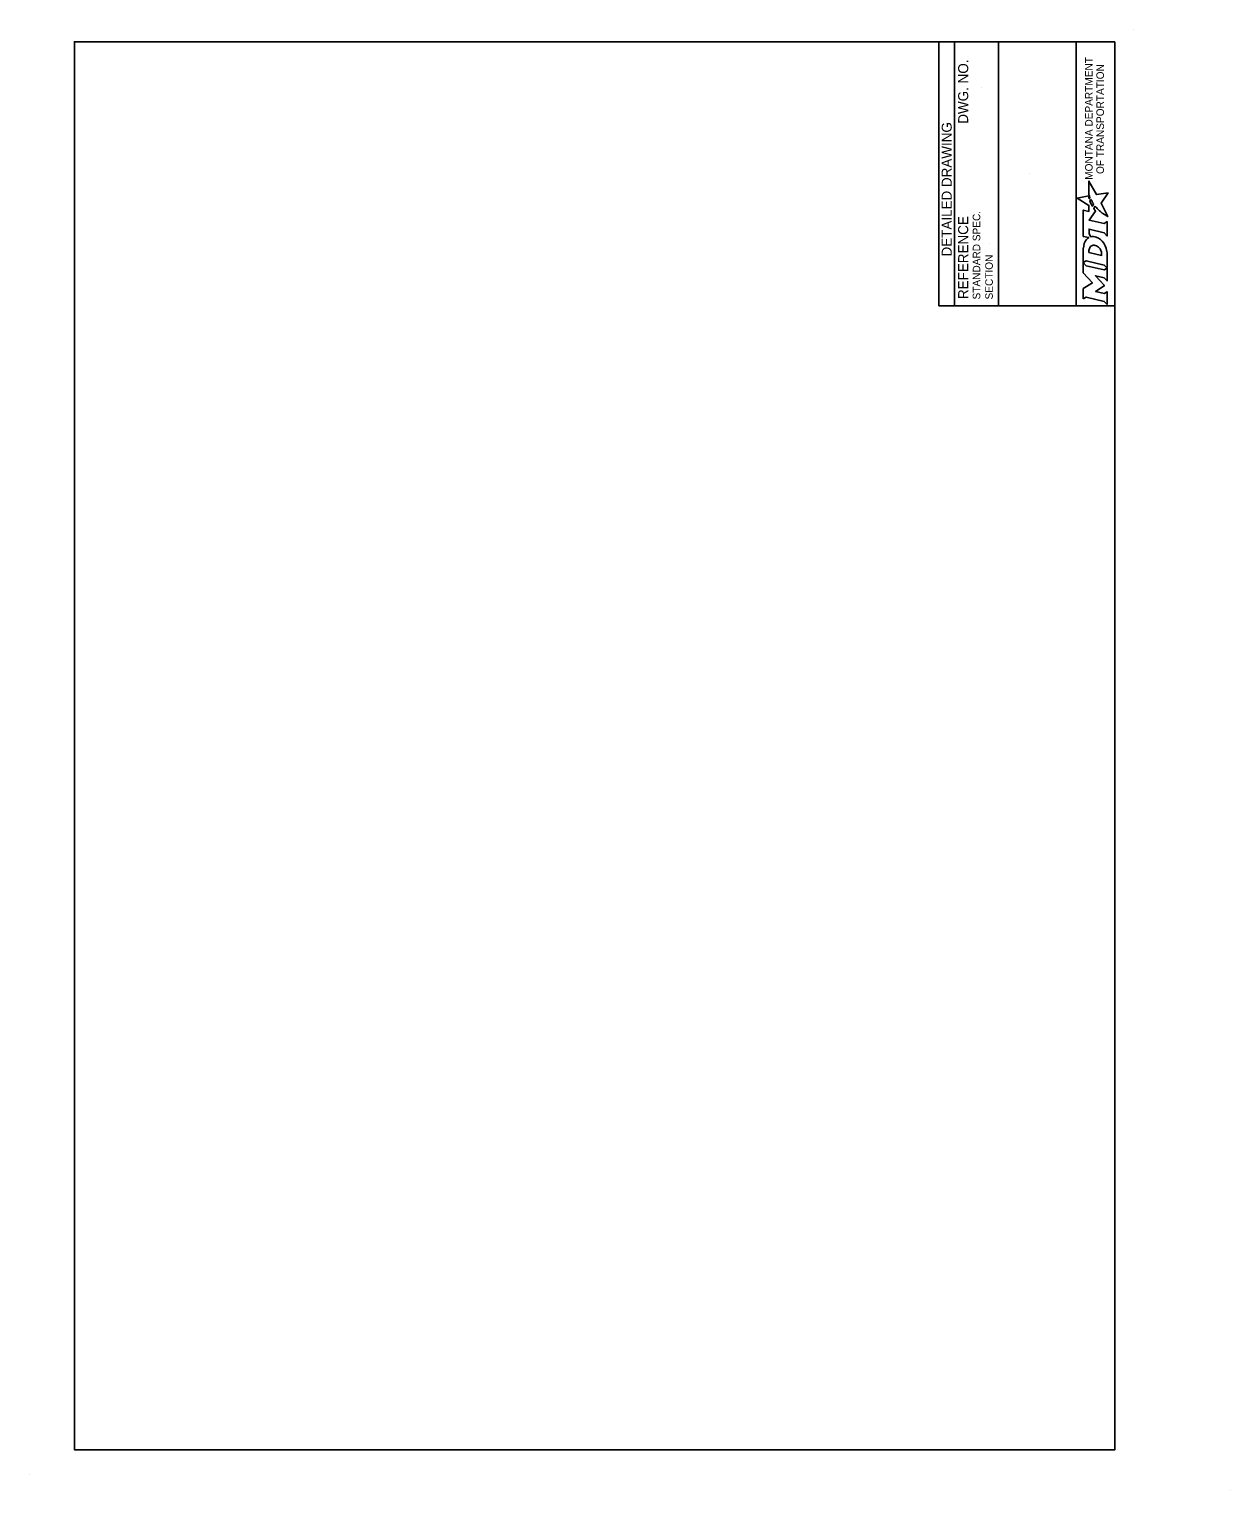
# Model space of a CAD drawing. Extents: x 49987.2 to 50044, y 49982.5 to 50011.4.
# Drawn here: x 49999.98 to 50009.54, y 49999.74 to 50011.36 of the extents above; entities that cross this region are included whole.
import ezdxf

# ---------------------------------------------------------------- set-up
doc = ezdxf.new("R2010")
doc.units = 0
doc.layers.add('Level 1', color=7, linetype='Continuous')
doc.layers.add('Level 3', color=7, linetype='Continuous')

msp = doc.modelspace()

# ---------------------------------------------------------------- linework, layer by layer
at = {"layer": 'Level 1'}
for p, q in [((50008.765, 50011.363), (50008.765, 50011.363)), ((49999.977, 49999.862), (49999.977, 49999.862)), ((50009.537, 49999.736), (50009.537, 49999.736))]:
    msp.add_line(p, q, dxfattribs=at)
msp.add_lwpolyline([(50008.615, 50011.263), (50000.336, 50011.263), (50000.336, 50000.062), (50008.615, 50000.062)], close=True, dxfattribs=at)
at = {"layer": 'Level 3'}
for p, q in [((50007.215, 50011.263), (50007.215, 50009.163)), ((50007.34, 50011.263), (50007.34, 50009.163)), ((50007.69, 50011.263), (50007.69, 50009.163)), ((50008.308, 50011.263), (50008.308, 50009.163)), ((50007.555, 50010.899), (50007.555, 50010.899)), ((50007.939, 50010.213), (50007.939, 50010.213)), ((50007.614, 50009.657), (50007.614, 50009.657)), ((50007.215, 50009.163), (50008.615, 50009.163))]:
    msp.add_line(p, q, dxfattribs=at)
for points in [[(50008.514, 50009.9), (50008.538, 50009.885), (50008.546, 50009.88), (50008.554, 50009.875), (50008.559, 50009.872), (50008.505, 50009.978), (50008.561, 50010.061), (50008.468, 50010.048), (50008.409, 50010.155), (50008.409, 50010.106), (50008.408, 50010.076), (50008.408, 50010.055), (50008.409, 50010.048), (50008.411, 50010.043), (50008.413, 50010.035), (50008.417, 50010.025)], [(50008.417, 50010.025), (50008.411, 50010.014), (50008.409, 50010.026), (50008.407, 50010.038), (50008.316, 50010.02), (50008.408, 50009.961), (50008.408, 50009.914), (50008.364, 50009.924), (50008.364, 50009.715), (50008.407, 50009.705), (50008.398, 50009.699)], [(50008.445, 50009.974), (50008.446, 50009.972), (50008.437, 50009.954), (50008.431, 50009.964), (50008.429, 50009.968), (50008.425, 50009.977), (50008.422, 50009.982), (50008.419, 50009.99), (50008.416, 50009.998), (50008.424, 50010.009), (50008.426, 50010.005), (50008.428, 50010.001), (50008.431, 50009.997), (50008.434, 50009.992), (50008.435, 50009.99), (50008.436, 50009.987), (50008.438, 50009.985), (50008.439, 50009.982), (50008.441, 50009.98), (50008.443, 50009.977), (50008.445, 50009.974)], [(50008.423, 50009.711), (50008.41, 50009.736), (50008.41, 50009.773), (50008.531, 50009.744), (50008.553, 50009.717), (50008.553, 50009.833), (50008.531, 50009.816), (50008.41, 50009.844), (50008.462, 50009.915), (50008.447, 50009.937), (50008.458, 50009.956)], [(50008.498, 50009.914), (50008.498, 50009.914)], [(50008.451, 50009.644), (50008.459, 50009.643), (50008.468, 50009.64), (50008.476, 50009.635), (50008.484, 50009.63), (50008.491, 50009.623), (50008.497, 50009.615), (50008.502, 50009.607), (50008.506, 50009.598), (50008.508, 50009.589), (50008.509, 50009.58), (50008.509, 50009.564), (50008.409, 50009.587), (50008.409, 50009.603), (50008.41, 50009.611), (50008.412, 50009.619), (50008.415, 50009.625), (50008.419, 50009.631), (50008.424, 50009.636), (50008.43, 50009.64), (50008.436, 50009.642), (50008.443, 50009.644), (50008.446, 50009.644), (50008.451, 50009.644)], [(50008.546, 50009.618), (50008.543, 50009.626), (50008.538, 50009.639), (50008.527, 50009.66)], [(50008.364, 50009.62), (50008.364, 50009.506), (50008.387, 50009.521), (50008.531, 50009.487), (50008.553, 50009.462), (50008.553, 50009.572)], [(50008.387, 50009.481), (50008.364, 50009.506), (50008.364, 50009.424), (50008.437, 50009.344), (50008.364, 50009.3), (50008.364, 50009.218)], [(50008.364, 50009.218), (50008.388, 50009.232), (50008.531, 50009.198), (50008.553, 50009.173), (50008.553, 50009.274), (50008.531, 50009.261), (50008.461, 50009.277), (50008.53, 50009.321), (50008.53, 50009.326), (50008.46, 50009.401), (50008.531, 50009.385), (50008.553, 50009.36), (50008.553, 50009.462), (50008.53, 50009.448), (50008.387, 50009.481)]]:
    msp.add_lwpolyline(points, dxfattribs=at)
for centre, radius, start, end in [((50008.443, 50009.643), 0.0709, 69.5329, 105.8582), ((50008.425, 50009.599), 0.118, 30.9103, 69.1383)]:
    msp.add_arc(centre, radius, start, end, dxfattribs=at)
for centre, major_axis, ratio, start_param, end_param in [((50008.468, 50009.945), (0.0097, -0.0112), 0.021651, 3.157348, 6.283185), ((50008.487, 50009.924), (0.0102, -0.0098), 0.016458, 3.141593, 6.279097), ((50008.506, 50009.907), (0.00806, -0.00694), 0.008222, 0, 3.137361), ((50008.412, 50009.618), (0.0037, 0.0834), 0.568097, 0.61298, 1.570796), ((50008.404, 50009.673), (0.0295, 0.0361), 0.469099, 1.225588, 1.570796), ((50008.405, 50009.573), (-0.148, 0), 0.987302, 3.139398, 3.456847)]:
    msp.add_ellipse(centre, major_axis=major_axis, ratio=ratio, start_param=start_param, end_param=end_param, dxfattribs=at)

# ---------------------------------------------------------------- texts
for s, height, p in [('DWG. NO.', 0.08, (50007.448, 50010.611)), ('MONTANA DEPARTMENT', 0.06, (50008.438, 50010.165)), ('OF TRANSPORTATION', 0.06, (50008.528, 50010.211)), ('DETAILED DRAWING', 0.0799, (50007.317, 50009.555)), ('REFERENCE', 0.08, (50007.448, 50009.216)), ('STANDARD SPEC.', 0.06, (50007.544, 50009.213)), ('SECTION', 0.06, (50007.644, 50009.213))]:
    msp.add_text(s, height=height, rotation=90, dxfattribs=at).set_placement(p)

doc.saveas('drawing.dxf')
